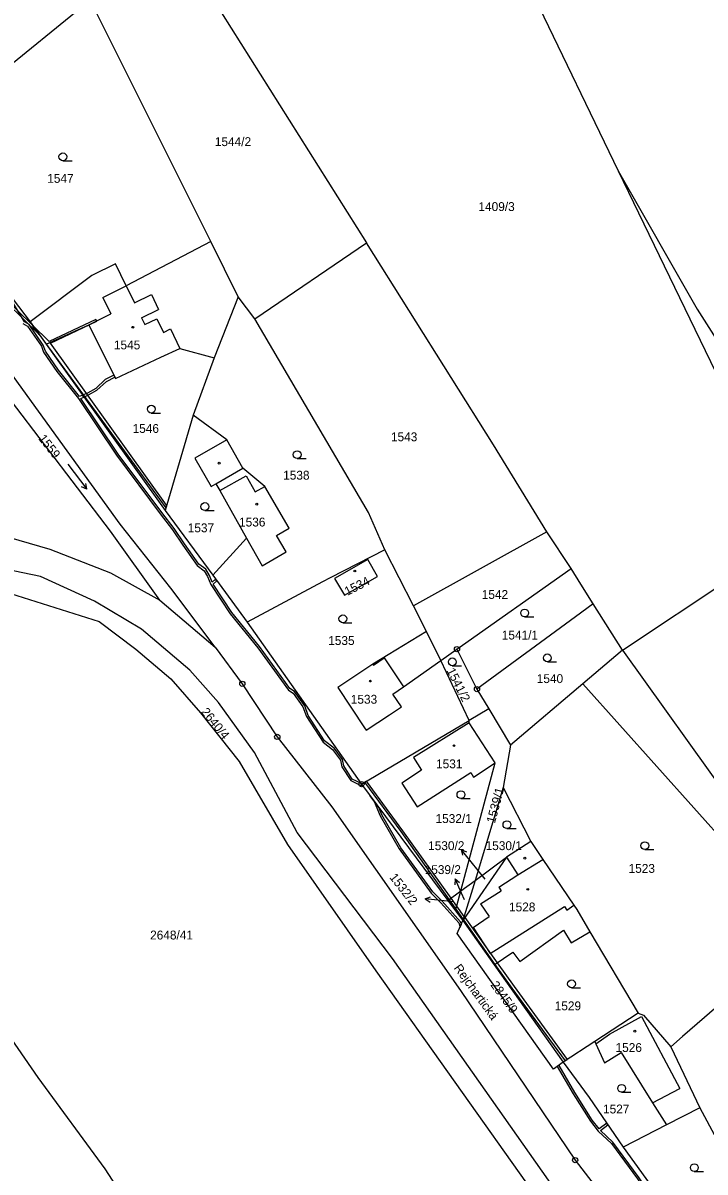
# Model space of a CAD drawing. Extents: x -562167 to -556918, y -1077891 to -1070763.
# Drawn here: x -560168.6 to -560037.8, y -1075431.3 to -1075211 of the extents above; entities that cross this region are included whole.
import ezdxf

# ---------------------------------------------------------------- set-up
doc = ezdxf.new("R2010")
doc.units = 0
for name, color, linetype in [('Hranice parcel', 7, 'Continuous'), ('Parcelní čísla', 7, 'Continuous'), ('Pop  PČ popisy', 7, 'Continuous'), ('Vnitřní kresba', 7, 'Continuous'), ('Věcná břemena k části', 7, 'Continuous'), ('Značky bodu BP', 7, 'Continuous'), ('Značky budov', 7, 'Continuous'), ('Značky kultur', 7, 'Continuous')]:
    doc.layers.add(name, color=color, linetype=linetype)

msp = doc.modelspace()

# ---------------------------------------------------------------- linework, layer by layer
at = {"layer": 'Hranice parcel'}
for p, q in [((-560093.71, -1075158.23), (-560054.48, -1075239.34)), ((-560138.04, -1075197.11), (-560102.77, -1075253.19)), ((-560179.25, -1075225.71), (-560156.69, -1075207.44)), ((-560132.62, -1075252.88), (-560155.7, -1075206.63)), ((-560054.48, -1075239.34), (-560021.84, -1075306.85)), ((-560127.32, -1075263.51), (-560132.62, -1075252.88)), ((-560124.14, -1075267.73), (-560102.77, -1075253.19)), ((-560127.32, -1075263.51), (-560131.97, -1075275.18)), ((-560124.14, -1075267.73), (-560127.32, -1075263.51)), ((-560167.24, -1075268.32), (-560164.18, -1075272.61)), ((-560164.18, -1075272.61), (-560141.37, -1075304.49)), ((-560131.97, -1075275.18), (-560135.97, -1075286.17)), ((-560135.97, -1075286.17), (-560141.37, -1075304.49)), ((-560129.55, -1075290.92), (-560135.97, -1075286.17)), ((-560141.37, -1075304.49), (-560132.21, -1075316.9)), ((-560068.13, -1075308.53), (-560093.7, -1075322.75)), ((-560063.48, -1075315.6), (-560068.13, -1075308.53)), ((-560053.65, -1075331.25), (-560020.67, -1075309.27)), ((-560132.21, -1075316.9), (-560125.73, -1075309.77)), ((-560093.7, -1075322.75), (-560099.22, -1075312.02)), ((-560085.39, -1075331.05), (-560063.48, -1075315.6)), ((-560132.21, -1075316.9), (-560125.6, -1075325.86)), ((-560142.4, -1075321.68), (-560131.73, -1075330.69)), ((-560053.65, -1075331.25), (-560059.25, -1075322.34)), ((-560091.26, -1075327.68), (-560093.7, -1075322.75)), ((-560125.6, -1075325.86), (-560103.7, -1075356.92)), ((-560088.5, -1075333.25), (-560091.26, -1075327.68)), ((-560088.5, -1075333.25), (-560085.39, -1075331.05)), ((-560085.39, -1075331.05), (-560081.56, -1075338.71)), ((-560053.65, -1075331.25), (-560061.25, -1075337.69)), ((-560053.65, -1075331.25), (-559994.74, -1075413.65)), ((-560083.07, -1075344.74), (-560088.5, -1075333.25)), ((-560061.25, -1075337.69), (-560075.15, -1075349.47)), ((-560018.93, -1075385.01), (-560061.25, -1075337.69)), ((-560081.56, -1075338.71), (-560079.3, -1075342.51)), ((-560079.3, -1075342.51), (-560083.07, -1075344.74)), ((-560079.3, -1075342.51), (-560075.15, -1075349.47)), ((-560103.7, -1075356.92), (-560083.07, -1075344.74)), ((-560083.05, -1075345.17), (-560083.07, -1075344.74)), ((-560078.05, -1075352.87), (-560083.05, -1075345.17)), ((-560075.15, -1075349.47), (-560076.56, -1075357.59)), ((-560084.62, -1075377.39), (-560078.05, -1075352.87)), ((-560103.7, -1075356.92), (-560087.12, -1075379.24)), ((-560076.56, -1075357.59), (-560081.93, -1075375.4)), ((-560076.56, -1075357.59), (-560071.25, -1075367.91)), ((-560071.25, -1075367.91), (-560075.91, -1075370.94)), ((-560075.91, -1075370.94), (-560084.25, -1075383.08)), ((-560081.93, -1075375.4), (-560075.91, -1075370.94)), ((-560084.62, -1075377.39), (-560081.93, -1075375.4)), ((-560081.93, -1075375.4), (-560084.25, -1075383.08)), ((-560087.12, -1075379.24), (-560084.62, -1075377.39)), ((-560085.65, -1075381.22), (-560084.62, -1075377.39)), ((-560087.12, -1075379.24), (-560085.65, -1075381.22)), ((-560085.65, -1075381.22), (-560084.25, -1075383.08)), ((-560085.33, -1075385.55), (-560084.25, -1075383.08)), ((-560084.25, -1075383.08), (-560078.26, -1075391.59)), ((-560066.86, -1075411.59), (-560085.33, -1075385.55)), ((-560059.9, -1075385.22), (-560050.66, -1075400.81)), ((-560078.26, -1075391.59), (-560065.03, -1075410.22)), ((-560050.66, -1075400.81), (-560058.94, -1075406.23)), ((-560058.94, -1075406.23), (-560065.03, -1075410.22)), ((-560044.4, -1075407.28), (-560038.81, -1075418.95)), ((-560065.03, -1075410.22), (-560066.86, -1075411.59)), ((-560038.81, -1075418.95), (-560045.22, -1075422.25)), ((-560038.81, -1075418.95), (-560025.55, -1075443.77)), ((-560045.22, -1075422.25), (-560053.5, -1075426.52))]:
    msp.add_line(p, q, dxfattribs=at)
for points in [[(-560185.83, -1075236.16), (-560170.49, -1075264.02), (-560167.24, -1075268.32)], [(-560054.48, -1075239.34), (-560039.36, -1075265.91), (-560021.83, -1075293.45)], [(-560132.62, -1075252.88), (-560148.82, -1075261.43), (-560150.88, -1075257.2), (-560155.39, -1075259.44), (-560167.24, -1075268.32)], [(-560068.13, -1075308.53), (-560078.41, -1075291.88), (-560102.77, -1075253.19)], [(-560142.4, -1075321.68), (-560151.85, -1075308.44), (-560189.85, -1075258.59), (-560186.88, -1075256.18)], [(-560131.73, -1075330.69), (-560140.28, -1075319.37), (-560149.99, -1075307.09), (-560186.88, -1075256.18)], [(-560164.18, -1075272.61), (-560155.97, -1075268.89), (-560150.9, -1075279.16), (-560142.17, -1075275.1), (-560138.56, -1075273.42), (-560131.97, -1075275.18)], [(-560099.22, -1075312.02), (-560102.37, -1075304.85), (-560124.14, -1075267.73)], [(-560239.53, -1075290.55), (-560217.71, -1075297.51), (-560180.89, -1075306.83), (-560163.49, -1075311.91), (-560151.81, -1075316.39), (-560142.4, -1075321.68)], [(-560129.55, -1075290.92), (-560135.65, -1075294.47), (-560132.51, -1075299.89), (-560131.61, -1075299.37), (-560130.88, -1075300.67), (-560125.73, -1075309.77)], [(-560125.73, -1075309.77), (-560122.74, -1075315.05), (-560118.16, -1075312.42), (-560119.98, -1075309.24), (-560117.55, -1075307.84), (-560122.24, -1075299.86), (-560126.45, -1075296.37), (-560129.55, -1075290.92)], [(-560045.55, -1075464.21), (-560067.84, -1075432.85), (-560097.73, -1075390.37), (-560116.01, -1075366.17), (-560124.2, -1075350.88), (-560131.1, -1075341.27), (-560136.59, -1075335.08), (-560145.89, -1075327.2), (-560154.9, -1075321.85), (-560165.27, -1075317.15), (-560182.25, -1075313.6), (-560219.76, -1075305.74), (-560242.79, -1075298.45)], [(-560126.48, -1075471.4), (-560152.86, -1075430.65), (-560165.73, -1075413.17), (-560188.91, -1075379.61), (-560209.38, -1075350.65), (-560229.71, -1075321.98), (-560243.08, -1075303.96)], [(-560243.08, -1075303.96), (-560226.06, -1075309.33), (-560196.59, -1075312.36), (-560154.01, -1075325.75)], [(-560099.22, -1075312.02), (-560109.71, -1075317.4), (-560111.16, -1075318.17), (-560125.6, -1075325.86)], [(-560100.62, -1075317.12), (-560102.46, -1075313.86), (-560108.9, -1075317.48), (-560106.98, -1075320.73), (-560100.62, -1075317.12)], [(-560059.25, -1075322.34), (-560061.61, -1075318.58), (-560063.48, -1075315.6)], [(-560059.25, -1075322.34), (-560062.64, -1075324.83), (-560081.56, -1075338.71)], [(-560154.01, -1075325.75), (-560146.95, -1075331.06), (-560140.23, -1075336.73), (-560134.57, -1075343.26), (-560127.18, -1075352.57), (-560117.89, -1075368.51), (-560100.98, -1075392.71), (-560070.64, -1075435.38), (-560055.13, -1075456.48)], [(-560091.26, -1075327.68), (-560101.52, -1075333.91), (-560108.26, -1075338.39), (-560103.13, -1075346.11), (-560102.82, -1075346.57), (-560098.32, -1075343.62), (-560096.02, -1075342.11), (-560097.67, -1075339.65), (-560095.65, -1075338.3), (-560088.5, -1075333.25)], [(-560131.73, -1075330.69), (-560126.56, -1075337.69), (-560119.85, -1075347.87), (-560109.4, -1075361.25), (-560084.71, -1075396.48), (-560062.73, -1075428.99), (-560041.77, -1075456.2), (-560040.33, -1075460.71)], [(-560083.05, -1075345.17), (-560093.75, -1075351.79), (-560092.21, -1075354.27), (-560095.99, -1075356.76), (-560093.04, -1075361.26), (-560082.75, -1075354.71), (-560082.19, -1075355.56), (-560078.05, -1075352.87)], [(-560071.25, -1075367.91), (-560068.93, -1075371.34), (-560062.98, -1075380.13), (-560062.42, -1075380.96), (-560059.9, -1075385.22)], [(-560078.26, -1075391.59), (-560074.68, -1075389.11), (-560073.34, -1075390.93), (-560064.93, -1075384.94), (-560063.5, -1075387.35), (-560059.9, -1075385.22)], [(-560023.37, -1075389.07), (-560042.15, -1075405.33), (-560044.4, -1075407.28)], [(-560050.66, -1075400.81), (-560049.59, -1075401.21), (-560044.4, -1075407.28)], [(-560058.94, -1075406.23), (-560058.73, -1075406.71), (-560057.11, -1075410.34), (-560053.93, -1075408.35), (-560047.87, -1075418.01), (-560045.22, -1075422.25)], [(-560065.03, -1075410.22), (-560060.04, -1075416.97), (-560053.5, -1075426.52)], [(-560053.5, -1075426.52), (-560046.18, -1075436.65), (-560040.41, -1075444.19), (-560033.57, -1075449.85)]]:
    msp.add_lwpolyline(points, dxfattribs=at)
at = {"layer": 'Pop  PČ popisy'}
for p, q in [((-560082.67, -1075371.8), (-560084.56, -1075369.47)), ((-560084.56, -1075369.47), (-560083.54, -1075369.93)), ((-560084.56, -1075369.47), (-560084.32, -1075370.56)), ((-560079.96, -1075375.15), (-560082.67, -1075371.8)), ((-560085.74, -1075375.08), (-560085.79, -1075376.2)), ((-560084.52, -1075377.82), (-560085.74, -1075375.08)), ((-560085.74, -1075375.08), (-560084.88, -1075375.79)), ((-560091.48, -1075378.92), (-560090.44, -1075378.52)), ((-560088.5, -1075379.23), (-560091.48, -1075378.92)), ((-560091.48, -1075378.92), (-560090.54, -1075379.52)), ((-560085.97, -1075379.5), (-560088.5, -1075379.23)), ((-560083.97, -1075379.08), (-560084.52, -1075377.82))]:
    msp.add_line(p, q, dxfattribs=at)
at = {"layer": 'Vnitřní kresba'}
for p, q in [((-560153.3, -1075263.65), (-560148.82, -1075261.43)), ((-560148.82, -1075261.43), (-560147.25, -1075264.65)), ((-560147.25, -1075264.65), (-560143.94, -1075263.04)), ((-560143.94, -1075263.04), (-560142.62, -1075265.93)), ((-560153.3, -1075263.65), (-560151.75, -1075266.79)), ((-560155.97, -1075268.89), (-560151.75, -1075266.79)), ((-560145.86, -1075267.51), (-560142.62, -1075265.93)), ((-560145.86, -1075267.51), (-560145.23, -1075268.81)), ((-560145.23, -1075268.81), (-560142.96, -1075267.71)), ((-560142.96, -1075267.71), (-560141.68, -1075270.33)), ((-560141.68, -1075270.33), (-560140.3, -1075269.66)), ((-560140.3, -1075269.66), (-560138.56, -1075273.42)), ((-560131.61, -1075299.37), (-560126.45, -1075296.37)), ((-560130.88, -1075300.67), (-560125.82, -1075297.81)), ((-560125.82, -1075297.81), (-560124.06, -1075300.9)), ((-560124.06, -1075300.9), (-560122.24, -1075299.86)), ((-560101.4, -1075334.09), (-560099.36, -1075332.72)), ((-560099.36, -1075332.72), (-560095.65, -1075338.3)), ((-560101.52, -1075333.91), (-560101.4, -1075334.09)), ((-560075.91, -1075370.94), (-560073.69, -1075374.34)), ((-560073.69, -1075374.34), (-560068.93, -1075371.34)), ((-560077.39, -1075376.68), (-560073.69, -1075374.34)), ((-560080.88, -1075379.9), (-560076.89, -1075377.35)), ((-560077.39, -1075376.68), (-560076.89, -1075377.35)), ((-560080.88, -1075379.9), (-560079.21, -1075382.32)), ((-560079.04, -1075389.4), (-560064.8, -1075380.38)), ((-560064.8, -1075380.38), (-560064.35, -1075381.06)), ((-560064.35, -1075381.06), (-560062.98, -1075380.13)), ((-560082.3, -1075384.42), (-560079.21, -1075382.32)), ((-560082.3, -1075384.42), (-560079.04, -1075389.4)), ((-560056.11, -1075404.88), (-560050.02, -1075401.46)), ((-560050.02, -1075401.46), (-560042.63, -1075415.24)), ((-560058.73, -1075406.71), (-560056.11, -1075404.88)), ((-560047.87, -1075418.01), (-560042.63, -1075415.24))]:
    msp.add_line(p, q, dxfattribs=at)
at = {"layer": 'Věcná břemena k části'}
for points in [[(-560194.55, -1075241.46), (-560193.79, -1075242.44), (-560194.15, -1075244.25), (-560193.79, -1075244.85), (-560193.62, -1075244.64), (-560193.4, -1075243.52), (-560165.5, -1075270.76), (-560166.81, -1075268.92), (-560193.3, -1075243.06), (-560193.09, -1075242.37), (-560195.07, -1075239.64), (-560196.26, -1075238.49), (-560196.9, -1075238.22), (-560196.55, -1075239.04), (-560195.53, -1075240.03)], [(-560166.81, -1075268.92), (-560165.5, -1075270.76), (-560141.21, -1075303.95), (-560141.07, -1075303.46), (-560163.32, -1075272.39), (-560154.48, -1075268.15), (-560154.63, -1075267.84), (-560163.58, -1075272.07)], [(-560157.18, -1075282.39), (-560156.94, -1075282.72), (-560156.06, -1075282.33), (-560154.42, -1075281.38), (-560152.6, -1075279.72), (-560151.02, -1075278.91), (-560151.2, -1075278.55), (-560152.84, -1075279.38), (-560154.66, -1075281.06), (-560156.24, -1075281.97)], [(-560103.1, -1075356.57), (-560096.14, -1075366.03), (-560086.89, -1075379.07), (-560086.5, -1075378.78), (-560095.78, -1075365.85), (-560102.76, -1075356.36)], [(-560100.39, -1075361.38), (-560102.05, -1075359.15), (-560101.3, -1075360.28), (-560100.14, -1075362.99), (-560096.5, -1075369.35), (-560090.33, -1075377.84), (-560088.48, -1075379.66), (-560085.06, -1075383.52), (-560084.79, -1075384.31), (-560084.55, -1075383.77), (-560084.7, -1075383.32), (-560088.2, -1075379.38), (-560090.03, -1075377.58), (-560096.16, -1075369.13), (-560099.78, -1075362.81)], [(-560086.89, -1075379.07), (-560085.57, -1075380.94), (-560084.19, -1075382.88), (-560084.15, -1075382.94), (-560078.1, -1075391.48), (-560074.84, -1075396.06), (-560064.65, -1075409.97), (-560064.22, -1075409.69), (-560074.34, -1075395.74), (-560077.63, -1075391.15), (-560083.84, -1075382.49), (-560084, -1075382.27), (-560085.41, -1075380.31), (-560086.5, -1075378.78)], [(-560065.82, -1075410.83), (-560066.16, -1075411.05), (-560063.12, -1075416.26), (-560059.78, -1075421.54), (-560058.31, -1075423.44), (-560055.77, -1075425.81), (-560050.74, -1075432.6), (-560047.14, -1075438.12), (-560039.55, -1075446.95), (-560038.4, -1075445.85), (-560038.71, -1075445.59), (-560039.53, -1075446.37), (-560046.82, -1075437.88), (-560050.42, -1075432.38), (-560055.47, -1075425.55), (-560057.85, -1075423.32), (-560056.43, -1075422.24), (-560056.65, -1075421.92), (-560058.12, -1075423.02), (-560059.46, -1075421.32), (-560062.78, -1075416.06)]]:
    msp.add_lwpolyline(points, close=True, dxfattribs=at)
msp.add_lwpolyline([(-560168.62, -1075268.62), (-560167.72, -1075269.15), (-560165.09, -1075272.98), (-560164.68, -1075274.11), (-560162.1, -1075277.83), (-560157.98, -1075283.02), (-560150.7, -1075293.89), (-560142.28, -1075305.12), (-560139.97, -1075308.16), (-560137.95, -1075311.09), (-560135.18, -1075315.02), (-560133.85, -1075316.02), (-560133.2, -1075317.12), (-560132.57, -1075318.64), (-560128.87, -1075324.29), (-560123.58, -1075330.77), (-560117.72, -1075338.88), (-560116.82, -1075339.47), (-560114.95, -1075342.12), (-560114.26, -1075343.95), (-560111.07, -1075348.88), (-560109.25, -1075350.28), (-560107.72, -1075352.34), (-560107.46, -1075353.58), (-560105.74, -1075356.24), (-560103.33, -1075357.42), (-560103.7, -1075356.92), (-560103.84, -1075356.72), (-560105.46, -1075355.94), (-560107.08, -1075353.42), (-560107.34, -1075352.18), (-560108.97, -1075350), (-560110.77, -1075348.6), (-560113.9, -1075343.77), (-560114.59, -1075341.94), (-560116.54, -1075339.17), (-560117.44, -1075338.58), (-560123.26, -1075330.53), (-560128.55, -1075324.05), (-560132.13, -1075318.58), (-560131.44, -1075317.95), (-560131.67, -1075317.63), (-560132.31, -1075318.21), (-560132.84, -1075316.94), (-560133.55, -1075315.74), (-560134.88, -1075314.74), (-560137.63, -1075310.87), (-560139.65, -1075307.92), (-560141.96, -1075304.88), (-560150.38, -1075293.65), (-560157.52, -1075282.98), (-560156.94, -1075282.72), (-560157.18, -1075282.39), (-560157.76, -1075282.65), (-560161.78, -1075277.59), (-560164.32, -1075273.93), (-560164.73, -1075272.8), (-560167.44, -1075268.85), (-560168.32, -1075268.32), (-560176.28, -1075255.18)], dxfattribs=at)
at = {"layer": 'Značky bodu BP'}
for centre, radius in [((-560085.39, -1075331.05), 0.5), ((-560085.39, -1075331.05), 0.0303), ((-560126.56, -1075337.69), 0.5), ((-560126.56, -1075337.69), 0.0303), ((-560081.56, -1075338.71), 0.5), ((-560081.56, -1075338.71), 0.0303), ((-560119.85, -1075347.87), 0.5), ((-560119.85, -1075347.87), 0.0303), ((-560103.7, -1075356.92), 0.5), ((-560103.7, -1075356.92), 0.0303), ((-560062.73, -1075428.99), 0.5), ((-560062.73, -1075428.99), 0.0303)]:
    msp.add_circle(centre, radius, dxfattribs=at)
at = {"layer": 'Značky budov'}
for centre in [(-560147.55, -1075269.35), (-560130.98, -1075295.4), (-560123.79, -1075303.26), (-560104.98, -1075316.07), (-560102, -1075337.17), (-560085.96, -1075349.55), (-560072.37, -1075371.13), (-560071.82, -1075377.09), (-560051.27, -1075404.28)]:
    msp.add_circle(centre, 0.175, dxfattribs=at)
at = {"layer": 'Značky kultur'}
for p, q in [((-560160.96, -1075237.42), (-560159.21, -1075237.42)), ((-560144.01, -1075285.79), (-560142.26, -1075285.79)), ((-560159.99, -1075295.6), (-560156.38, -1075300.4)), ((-560116.03, -1075294.51), (-560114.28, -1075294.51)), ((-560156.38, -1075300.4), (-560157.37, -1075299.92)), ((-560156.38, -1075300.4), (-560156.57, -1075299.31)), ((-560133.73, -1075304.47), (-560131.98, -1075304.47)), ((-560107.27, -1075325.98), (-560105.52, -1075325.98)), ((-560072.42, -1075324.86), (-560070.67, -1075324.86)), ((-560068.06, -1075333.47), (-560066.31, -1075333.47)), ((-560086.28, -1075334.24), (-560084.53, -1075334.24)), ((-560084.63, -1075359.69), (-560082.88, -1075359.69)), ((-560075.81, -1075365.44), (-560074.06, -1075365.44)), ((-560049.37, -1075369.46), (-560047.62, -1075369.46)), ((-560063.42, -1075395.96), (-560061.67, -1075395.96)), ((-560053.81, -1075415.99), (-560052.06, -1075415.99)), ((-560039.88, -1075431.18), (-560038.13, -1075431.18))]:
    msp.add_line(p, q, dxfattribs=at)
for centre in [(-560160.96, -1075236.67), (-560144.01, -1075285.04), (-560116.03, -1075293.76), (-560133.73, -1075303.72), (-560107.27, -1075325.23), (-560072.42, -1075324.11), (-560086.28, -1075333.49), (-560068.06, -1075332.72), (-560084.63, -1075358.94), (-560075.81, -1075364.69), (-560049.37, -1075368.71), (-560063.42, -1075395.21), (-560053.81, -1075415.24), (-560039.88, -1075430.43)]:
    msp.add_circle(centre, 0.75, dxfattribs=at)

# ---------------------------------------------------------------- texts
at = {"layer": 'Parcelní čísla'}
for s, p in [('1544/2', (-560131.82, -1075234.62)), ('1547', (-560163.96, -1075241.66)), ('1409/3', (-560081.27, -1075247.07)), ('1545', (-560151.18, -1075273.59)), ('1546', (-560147.59, -1075289.6)), ('1543', (-560098.05, -1075291.2)), ('1538', (-560118.72, -1075298.56)), ('1537', (-560137.02, -1075308.65)), ('1536', (-560127.18, -1075307.54)), ('1542', (-560080.64, -1075321.42)), ('1535', (-560110.08, -1075330.25)), ('1541/1', (-560076.8, -1075329.2)), ('1540', (-560070.09, -1075337.55)), ('1533', (-560105.75, -1075341.51)), ('1531', (-560089.4, -1075353.89)), ('1532/1', (-560089.5, -1075364.38)), ('1530/2', (-560090.92, -1075369.57)), ('1530/1', (-560079.9, -1075369.57)), ('1539/2', (-560091.59, -1075374.16)), ('1523', (-560052.48, -1075373.93)), ('1528', (-560075.41, -1075381.32)), ('2648/41', (-560144.23, -1075386.7)), ('1529', (-560066.65, -1075400.28)), ('1526', (-560054.98, -1075408.27)), ('1527', (-560057.38, -1075420.05))]:
    msp.add_text(s, height=1.7, dxfattribs=at).set_placement(p)
for s, rotation, p in [('1559', 308, (-560165.76, -1075290.7)), ('1534', 27, (-560106.43, -1075320.85)), ('1541/2', 297, (-560087.44, -1075335.15)), ('2640/4', 309, (-560134.57, -1075343.11)), ('1539/1', 75, (-560078.13, -1075364.54)), ('1532/2', 308, (-560098.43, -1075374.82)), ('2845/9', 306, (-560079.04, -1075395.43))]:
    msp.add_text(s, height=1.7, rotation=rotation, dxfattribs=at).set_placement(p)
at = {"layer": 'Pop  PČ popisy'}
msp.add_text('Rejchartická', height=1.7, rotation=306, dxfattribs=at).set_placement((-560086.07, -1075392.18))

doc.saveas('drawing.dxf')
